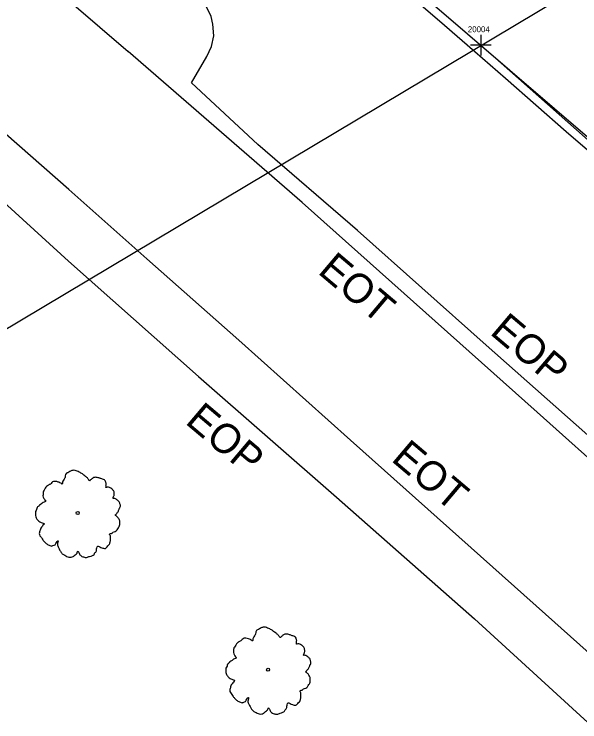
# Model space of a CAD drawing. Extents: x 2076109 to 2080761, y 592812 to 596750.
# Drawn here: x 2077285.2 to 2077381.1, y 595618.3 to 595738.3 of the extents above; entities that cross this region are included whole.
import ezdxf

# ---------------------------------------------------------------- set-up
doc = ezdxf.new("R2010")
doc.units = 0
for name, color, linetype in [('Default', 7, 'Continuous'), ('RD_EX_Misc', 7, 'Continuous'), ('RD_EX_Misc_txCode', 7, 'Continuous'), ('RD_EX_Road', 7, 'Continuous'), ('RD_EX_Road_txCode', 7, 'Continuous'), ('RD_EX_UT', 7, 'Continuous'), ('RD_EX_VEG', 7, 'Continuous'), ('RD_HC_Cl', 7, 'Continuous')]:
    doc.layers.add(name, color=color, linetype=linetype)

msp = doc.modelspace()

# ---------------------------------------------------------------- linework, layer by layer
at = {"layer": 'Default'}
for p, q in [((2077364.31, 595734.81), (2077364.31, 595731.31)), ((2077364.31, 595734.81), (2077364.31, 595731.31)), ((2077364.31, 595734.81), (2077364.31, 595731.31)), ((2077364.31, 595734.81), (2077364.31, 595731.31)), ((2077366.06, 595733.06), (2077362.56, 595733.06)), ((2077366.06, 595733.06), (2077362.56, 595733.06)), ((2077366.06, 595733.06), (2077362.56, 595733.06)), ((2077366.06, 595733.06), (2077362.56, 595733.06)), ((2077364.31, 595733.06), (2078453.96, 594769.07)), ((2077364.31, 595733.06), (2078453.96, 594769.07))]:
    msp.add_line(p, q, dxfattribs=at)
msp.add_arc((2035586.7, 547847.96), 63546.51, 48.5011873, 49.2923126, dxfattribs=at)
msp.add_arc((2035586.7, 547847.96), 63546.51, 48.5011873, 49.2923126, dxfattribs=at)
at = {"layer": 'RD_EX_Misc'}
for points in [[(2077285.72, 595748.24), (2077304.56, 595732)], [(2077285.72, 595748.24), (2077304.56, 595732)], [(2077294.47, 595708.58), (2077270.77, 595729.36), (2077263.48, 595735.7)], [(2077294.47, 595708.58), (2077270.77, 595729.36), (2077263.48, 595735.7)], [(2077850.7, 595201.63), (2077820.53, 595232.8), (2077790.22, 595263.88), (2077762.8, 595291.76), (2077736.42, 595318.96), (2077709.92, 595346.36), (2077678.72, 595378.46), (2077649.91, 595408.22), (2077612.46, 595446.3), (2077577.19, 595481.07), (2077550.3, 595507.41), (2077509.12, 595546.77), (2077481.37, 595572.73), (2077443, 595608.1), (2077400.67, 595646.86), (2077373.88, 595670.82), (2077334.03, 595706.37), (2077304.56, 595732)], [(2077850.7, 595201.63), (2077820.53, 595232.8), (2077790.22, 595263.88), (2077762.8, 595291.76), (2077736.42, 595318.96), (2077709.92, 595346.36), (2077678.72, 595378.46), (2077649.91, 595408.22), (2077612.46, 595446.3), (2077577.19, 595481.07), (2077550.3, 595507.41), (2077509.12, 595546.77), (2077481.37, 595572.73), (2077443, 595608.1), (2077400.67, 595646.86), (2077373.88, 595670.82), (2077334.03, 595706.37), (2077304.56, 595732)], [(2077812.69, 595205.74), (2077779.15, 595240.73), (2077743.86, 595277.34), (2077707.16, 595314.93), (2077677.78, 595345.17), (2077641.95, 595381.51), (2077607.57, 595416.21), (2077570.67, 595452.82), (2077540.71, 595482.36), (2077500.4, 595521.29), (2077469.88, 595550.44), (2077431.8, 595585.6), (2077401.7, 595612.91), (2077373.73, 595637.96), (2077342.22, 595666.06), (2077323.28, 595683.05), (2077307.69, 595696.83), (2077294.47, 595708.58)], [(2077812.69, 595205.74), (2077779.15, 595240.73), (2077743.86, 595277.34), (2077707.16, 595314.93), (2077677.78, 595345.17), (2077641.95, 595381.51), (2077607.57, 595416.21), (2077570.67, 595452.82), (2077540.71, 595482.36), (2077500.4, 595521.29), (2077469.88, 595550.44), (2077431.8, 595585.6), (2077401.7, 595612.91), (2077373.73, 595637.96), (2077342.22, 595666.06), (2077323.28, 595683.05), (2077307.69, 595696.83), (2077294.47, 595708.58)]]:
    msp.add_lwpolyline(points, dxfattribs=at)
at = {"layer": 'RD_EX_Road'}
for points in [[(2077528.44, 595532.32), (2077507.93, 595551.7), (2077491.72, 595567.02), (2077467.24, 595590.18), (2077449.74, 595606.14), (2077431.68, 595622.71), (2077417.63, 595635.43), (2077400.96, 595650.59), (2077383.92, 595665.65), (2077365.24, 595682.19), (2077343.44, 595701.66), (2077326.52, 595716.21), (2077315.27, 595726.7), (2077317.91, 595731.12), (2077318.69, 595732.86), (2077319.09, 595734.63), (2077318.89, 595736.63), (2077318.61, 595737.93), (2077317.61, 595740.01), (2077315.19, 595742.84)], [(2077528.44, 595532.32), (2077507.93, 595551.7), (2077491.72, 595567.02), (2077467.24, 595590.18), (2077449.74, 595606.14), (2077431.68, 595622.71), (2077417.63, 595635.43), (2077400.96, 595650.59), (2077383.92, 595665.65), (2077365.24, 595682.19), (2077343.44, 595701.66), (2077326.52, 595716.21), (2077315.27, 595726.7), (2077317.91, 595731.12), (2077318.69, 595732.86), (2077319.09, 595734.63), (2077318.89, 595736.63), (2077318.61, 595737.93), (2077317.61, 595740.01), (2077315.19, 595742.84)], [(2077277.58, 595711.76), (2077294.44, 595696.44), (2077316.48, 595676.87), (2077339.86, 595656.39), (2077363.23, 595635.78), (2077381.85, 595618.74), (2077401.46, 595601.04), (2077426.38, 595578.58), (2077449.29, 595557.26), (2077472.1, 595535.89), (2077492.72, 595516.55), (2077515.1, 595494.99), (2077537.08, 595473.82), (2077562.41, 595448.47), (2077584.67, 595425.87), (2077605.91, 595404.49), (2077629.68, 595380.24), (2077656.48, 595352.83), (2077679.73, 595328.95), (2077700.7, 595307.57), (2077723.07, 595284.36), (2077743.1, 595263.78)], [(2077277.58, 595711.76), (2077294.44, 595696.44), (2077316.48, 595676.87), (2077339.86, 595656.39), (2077363.23, 595635.78), (2077381.85, 595618.74), (2077401.46, 595601.04), (2077426.38, 595578.58), (2077449.29, 595557.26), (2077472.1, 595535.89), (2077492.72, 595516.55), (2077515.1, 595494.99), (2077537.08, 595473.82), (2077562.41, 595448.47), (2077584.67, 595425.87), (2077605.91, 595404.49), (2077629.68, 595380.24), (2077656.48, 595352.83), (2077679.73, 595328.95), (2077700.7, 595307.57), (2077723.07, 595284.36), (2077743.1, 595263.78)]]:
    msp.add_lwpolyline(points, dxfattribs=at)
at = {"layer": 'RD_EX_UT'}
msp.add_line((2077214.8, 595643.67), (2077512.89, 595821.92), dxfattribs=at)
msp.add_line((2077214.8, 595643.67), (2077512.89, 595821.92), dxfattribs=at)
at = {"layer": 'RD_EX_VEG'}
for centre, radius in [((2077295.99, 595653.73), 0.25), ((2077295.99, 595653.73), 0.25), ((2077295.97, 595653.72), 0.0001), ((2077295.97, 595653.72), 0.0001), ((2077328.27, 595627.15), 0.25), ((2077328.27, 595627.15), 0.25), ((2077328.25, 595627.14), 0.0001), ((2077328.25, 595627.14), 0.0001)]:
    msp.add_circle(centre, radius, dxfattribs=at)
for points in [[(2077300.72, 595659.12), (2077300.51, 595659.33), (2077300.2, 595659.46), (2077299.94, 595659.55), (2077299.72, 595659.64), (2077299.48, 595659.7), (2077299.14, 595659.77), (2077298.84, 595659.76), (2077298.58, 595659.65), (2077298.4, 595659.51), (2077298.19, 595659.33), (2077298.07, 595659.2), (2077297.96, 595659.26), (2077297.86, 595659.37), (2077297.72, 595659.59), (2077297.53, 595659.75), (2077297.34, 595659.92), (2077297.06, 595660.12), (2077296.79, 595660.35), (2077296.55, 595660.49), (2077296.27, 595660.66), (2077295.9, 595660.81), (2077295.55, 595660.94), (2077295.16, 595660.94), (2077294.66, 595660.74), (2077294.34, 595660.55), (2077294.07, 595660.46), (2077293.89, 595660.02), (2077293.8, 595659.64), (2077293.69, 595659.47), (2077293.47, 595659.1), (2077293.4, 595658.86), (2077293.37, 595658.63), (2077293.29, 595658.66), (2077292.98, 595658.86), (2077292.68, 595658.98), (2077292.21, 595659.08), (2077291.9, 595659.06), (2077291.61, 595658.87), (2077291.36, 595658.62), (2077291.16, 595658.53), (2077290.92, 595658.37), (2077290.86, 595658.33), (2077290.61, 595658.11), (2077290.39, 595657.71), (2077290.19, 595657.42), (2077290.14, 595657.17), (2077290.14, 595656.94), (2077290.11, 595656.64), (2077290.27, 595656.21), (2077290.45, 595655.92), (2077290.59, 595655.77), (2077290.13, 595655.5), (2077289.87, 595655.27), (2077289.52, 595655.05), (2077289.47, 595654.99), (2077289.12, 595654.66), (2077289.03, 595654.31), (2077288.84, 595653.98), (2077288.83, 595653.69), (2077288.85, 595653.29), (2077288.95, 595652.91), (2077289.25, 595652.49), (2077289.57, 595652.25), (2077290.12, 595652.01), (2077290.36, 595651.91), (2077290.23, 595651.79), (2077290.01, 595651.49), (2077289.73, 595651.16), (2077289.64, 595650.82), (2077289.54, 595650.54), (2077289.49, 595650.26), (2077289.59, 595649.87), (2077289.85, 595649.56), (2077290.08, 595649.17), (2077290.37, 595648.82), (2077290.74, 595648.48), (2077291.29, 595648.21), (2077291.58, 595648.12), (2077291.77, 595648.19), (2077292.17, 595648.35), (2077292.27, 595648.55), (2077292.68, 595649), (2077292.64, 595648.8), (2077292.55, 595648.42), (2077292.74, 595647.87), (2077292.93, 595647.47), (2077293.2, 595647.05), (2077293.38, 595646.8), (2077293.79, 595646.55), (2077294.12, 595646.37), (2077294.49, 595646.22), (2077294.9, 595646.24), (2077295.21, 595646.33), (2077295.42, 595646.51), (2077295.72, 595646.75), (2077295.87, 595646.85)], [(2077300.72, 595659.12), (2077300.51, 595659.33), (2077300.2, 595659.46), (2077299.94, 595659.55), (2077299.72, 595659.64), (2077299.48, 595659.7), (2077299.14, 595659.77), (2077298.84, 595659.76), (2077298.58, 595659.65), (2077298.4, 595659.51), (2077298.19, 595659.33), (2077298.07, 595659.2), (2077297.96, 595659.26), (2077297.86, 595659.37), (2077297.72, 595659.59), (2077297.53, 595659.75), (2077297.34, 595659.92), (2077297.06, 595660.12), (2077296.79, 595660.35), (2077296.55, 595660.49), (2077296.27, 595660.66), (2077295.9, 595660.81), (2077295.55, 595660.94), (2077295.16, 595660.94), (2077294.66, 595660.74), (2077294.34, 595660.55), (2077294.07, 595660.46), (2077293.89, 595660.02), (2077293.8, 595659.64), (2077293.69, 595659.47), (2077293.47, 595659.1), (2077293.4, 595658.86), (2077293.37, 595658.63), (2077293.29, 595658.66), (2077292.98, 595658.86), (2077292.68, 595658.98), (2077292.21, 595659.08), (2077291.9, 595659.06), (2077291.61, 595658.87), (2077291.36, 595658.62), (2077291.16, 595658.53), (2077290.92, 595658.37), (2077290.86, 595658.33), (2077290.61, 595658.11), (2077290.39, 595657.71), (2077290.19, 595657.42), (2077290.14, 595657.17), (2077290.14, 595656.94), (2077290.11, 595656.64), (2077290.27, 595656.21), (2077290.45, 595655.92), (2077290.59, 595655.77), (2077290.13, 595655.5), (2077289.87, 595655.27), (2077289.52, 595655.05), (2077289.47, 595654.99), (2077289.12, 595654.66), (2077289.03, 595654.31), (2077288.84, 595653.98), (2077288.83, 595653.69), (2077288.85, 595653.29), (2077288.95, 595652.91), (2077289.25, 595652.49), (2077289.57, 595652.25), (2077290.12, 595652.01), (2077290.36, 595651.91), (2077290.23, 595651.79), (2077290.01, 595651.49), (2077289.73, 595651.16), (2077289.64, 595650.82), (2077289.54, 595650.54), (2077289.49, 595650.26), (2077289.59, 595649.87), (2077289.85, 595649.56), (2077290.08, 595649.17), (2077290.37, 595648.82), (2077290.74, 595648.48), (2077291.29, 595648.21), (2077291.58, 595648.12), (2077291.77, 595648.19), (2077292.17, 595648.35), (2077292.27, 595648.55), (2077292.68, 595649), (2077292.64, 595648.8), (2077292.55, 595648.42), (2077292.74, 595647.87), (2077292.93, 595647.47), (2077293.2, 595647.05), (2077293.38, 595646.8), (2077293.79, 595646.55), (2077294.12, 595646.37), (2077294.49, 595646.22), (2077294.9, 595646.24), (2077295.21, 595646.33), (2077295.42, 595646.51), (2077295.72, 595646.75), (2077295.87, 595646.85)], [(2077295.87, 595646.85), (2077295.93, 595647.03), (2077296.05, 595647.26), (2077296.09, 595647.19), (2077296.19, 595647.04), (2077296.32, 595646.76), (2077296.45, 595646.56), (2077296.71, 595646.37), (2077296.99, 595646.27), (2077297.51, 595646.19), (2077298.02, 595646.37), (2077298.49, 595646.5), (2077298.76, 595646.7), (2077298.87, 595646.9), (2077299.17, 595647.3), (2077299.18, 595647.62), (2077299.22, 595647.75), (2077299.4, 595648.12), (2077299.49, 595648.11), (2077299.73, 595647.97), (2077300.1, 595647.82), (2077300.39, 595647.74), (2077300.68, 595647.73), (2077300.88, 595647.85), (2077301.12, 595648.17), (2077301.41, 595648.45), (2077301.45, 595648.61), (2077301.47, 595648.79), (2077301.55, 595648.99), (2077301.53, 595649.2), (2077301.55, 595649.38), (2077301.54, 595649.52), (2077301.54, 595649.72), (2077301.49, 595649.92), (2077301.4, 595650.06), (2077301.46, 595650.21), (2077301.71, 595650.26), (2077301.81, 595650.31), (2077301.97, 595650.46), (2077302.37, 595650.58), (2077302.67, 595650.86), (2077302.9, 595651.21), (2077303.04, 595651.45), (2077303.11, 595651.76), (2077303.12, 595652.08), (2077303.13, 595652.3), (2077303.08, 595652.5), (2077302.91, 595652.81), (2077302.75, 595653.01), (2077302.49, 595653.23), (2077302.37, 595653.4), (2077302.42, 595653.42), (2077302.52, 595653.54), (2077302.69, 595653.75), (2077302.93, 595654.14), (2077303.13, 595654.62), (2077303.15, 595654.64), (2077303.24, 595654.89), (2077303.19, 595655.19), (2077303.12, 595655.38), (2077303.05, 595655.6), (2077302.88, 595655.79), (2077302.65, 595655.98), (2077302.41, 595656.12), (2077302.19, 595656.17), (2077301.98, 595656.19), (2077302.02, 595656.35), (2077302.13, 595656.65), (2077302.19, 595656.79), (2077302.19, 595657.02), (2077302.15, 595657.32), (2077301.88, 595657.71), (2077301.36, 595658.05), (2077301, 595658.09), (2077300.77, 595658.06), (2077300.82, 595658.18), (2077300.79, 595658.47), (2077300.83, 595658.66), (2077300.78, 595658.87), (2077300.73, 595659.05), (2077300.68, 595659.15)], [(2077295.87, 595646.85), (2077295.93, 595647.03), (2077296.05, 595647.26), (2077296.09, 595647.19), (2077296.19, 595647.04), (2077296.32, 595646.76), (2077296.45, 595646.56), (2077296.71, 595646.37), (2077296.99, 595646.27), (2077297.51, 595646.19), (2077298.02, 595646.37), (2077298.49, 595646.5), (2077298.76, 595646.7), (2077298.87, 595646.9), (2077299.17, 595647.3), (2077299.18, 595647.62), (2077299.22, 595647.75), (2077299.4, 595648.12), (2077299.49, 595648.11), (2077299.73, 595647.97), (2077300.1, 595647.82), (2077300.39, 595647.74), (2077300.68, 595647.73), (2077300.88, 595647.85), (2077301.12, 595648.17), (2077301.41, 595648.45), (2077301.45, 595648.61), (2077301.47, 595648.79), (2077301.55, 595648.99), (2077301.53, 595649.2), (2077301.55, 595649.38), (2077301.54, 595649.52), (2077301.54, 595649.72), (2077301.49, 595649.92), (2077301.4, 595650.06), (2077301.46, 595650.21), (2077301.71, 595650.26), (2077301.81, 595650.31), (2077301.97, 595650.46), (2077302.37, 595650.58), (2077302.67, 595650.86), (2077302.9, 595651.21), (2077303.04, 595651.45), (2077303.11, 595651.76), (2077303.12, 595652.08), (2077303.13, 595652.3), (2077303.08, 595652.5), (2077302.91, 595652.81), (2077302.75, 595653.01), (2077302.49, 595653.23), (2077302.37, 595653.4), (2077302.42, 595653.42), (2077302.52, 595653.54), (2077302.69, 595653.75), (2077302.93, 595654.14), (2077303.13, 595654.62), (2077303.15, 595654.64), (2077303.24, 595654.89), (2077303.19, 595655.19), (2077303.12, 595655.38), (2077303.05, 595655.6), (2077302.88, 595655.79), (2077302.65, 595655.98), (2077302.41, 595656.12), (2077302.19, 595656.17), (2077301.98, 595656.19), (2077302.02, 595656.35), (2077302.13, 595656.65), (2077302.19, 595656.79), (2077302.19, 595657.02), (2077302.15, 595657.32), (2077301.88, 595657.71), (2077301.36, 595658.05), (2077301, 595658.09), (2077300.77, 595658.06), (2077300.82, 595658.18), (2077300.79, 595658.47), (2077300.83, 595658.66), (2077300.78, 595658.87), (2077300.73, 595659.05), (2077300.68, 595659.15)], [(2077333, 595632.53), (2077332.79, 595632.74), (2077332.48, 595632.88), (2077332.22, 595632.96), (2077332, 595633.05), (2077331.77, 595633.12), (2077331.42, 595633.18), (2077331.12, 595633.17), (2077330.87, 595633.06), (2077330.68, 595632.92), (2077330.47, 595632.75), (2077330.35, 595632.61), (2077330.24, 595632.67), (2077330.14, 595632.79), (2077330, 595633.01), (2077329.81, 595633.17), (2077329.62, 595633.33), (2077329.34, 595633.54), (2077329.07, 595633.76), (2077328.83, 595633.9), (2077328.55, 595634.08), (2077328.18, 595634.22), (2077327.83, 595634.35), (2077327.44, 595634.36), (2077326.95, 595634.16), (2077326.62, 595633.97), (2077326.35, 595633.88), (2077326.17, 595633.43), (2077326.08, 595633.05), (2077325.97, 595632.89), (2077325.75, 595632.51), (2077325.68, 595632.28), (2077325.65, 595632.04), (2077325.58, 595632.07), (2077325.26, 595632.28), (2077324.96, 595632.39), (2077324.5, 595632.5), (2077324.18, 595632.47), (2077323.89, 595632.29), (2077323.65, 595632.04), (2077323.44, 595631.95), (2077323.21, 595631.79), (2077323.14, 595631.75), (2077322.89, 595631.53), (2077322.68, 595631.12), (2077322.47, 595630.84), (2077322.42, 595630.59), (2077322.42, 595630.36), (2077322.39, 595630.05), (2077322.55, 595629.62), (2077322.74, 595629.34), (2077322.87, 595629.19), (2077322.42, 595628.92), (2077322.15, 595628.69), (2077321.8, 595628.46), (2077321.75, 595628.4), (2077321.41, 595628.07), (2077321.31, 595627.73), (2077321.13, 595627.39), (2077321.11, 595627.11), (2077321.13, 595626.7), (2077321.23, 595626.32), (2077321.53, 595625.9), (2077321.85, 595625.66), (2077322.41, 595625.43), (2077322.65, 595625.32), (2077322.51, 595625.2), (2077322.29, 595624.9), (2077322.02, 595624.58), (2077321.92, 595624.23), (2077321.82, 595623.96), (2077321.77, 595623.67), (2077321.88, 595623.29), (2077322.13, 595622.97), (2077322.36, 595622.59), (2077322.65, 595622.24), (2077323.02, 595621.9), (2077323.57, 595621.62), (2077323.86, 595621.54), (2077324.05, 595621.61), (2077324.45, 595621.77), (2077324.56, 595621.97), (2077324.96, 595622.41), (2077324.93, 595622.21), (2077324.83, 595621.83), (2077325.02, 595621.28), (2077325.21, 595620.89), (2077325.48, 595620.47), (2077325.66, 595620.22), (2077326.07, 595619.97), (2077326.4, 595619.78), (2077326.77, 595619.64), (2077327.18, 595619.65), (2077327.49, 595619.75), (2077327.7, 595619.93), (2077328, 595620.16), (2077328.16, 595620.27)], [(2077333, 595632.53), (2077332.79, 595632.74), (2077332.48, 595632.88), (2077332.22, 595632.96), (2077332, 595633.05), (2077331.77, 595633.12), (2077331.42, 595633.18), (2077331.12, 595633.17), (2077330.87, 595633.06), (2077330.68, 595632.92), (2077330.47, 595632.75), (2077330.35, 595632.61), (2077330.24, 595632.67), (2077330.14, 595632.79), (2077330, 595633.01), (2077329.81, 595633.17), (2077329.62, 595633.33), (2077329.34, 595633.54), (2077329.07, 595633.76), (2077328.83, 595633.9), (2077328.55, 595634.08), (2077328.18, 595634.22), (2077327.83, 595634.35), (2077327.44, 595634.36), (2077326.95, 595634.16), (2077326.62, 595633.97), (2077326.35, 595633.88), (2077326.17, 595633.43), (2077326.08, 595633.05), (2077325.97, 595632.89), (2077325.75, 595632.51), (2077325.68, 595632.28), (2077325.65, 595632.04), (2077325.58, 595632.07), (2077325.26, 595632.28), (2077324.96, 595632.39), (2077324.5, 595632.5), (2077324.18, 595632.47), (2077323.89, 595632.29), (2077323.65, 595632.04), (2077323.44, 595631.95), (2077323.21, 595631.79), (2077323.14, 595631.75), (2077322.89, 595631.53), (2077322.68, 595631.12), (2077322.47, 595630.84), (2077322.42, 595630.59), (2077322.42, 595630.36), (2077322.39, 595630.05), (2077322.55, 595629.62), (2077322.74, 595629.34), (2077322.87, 595629.19), (2077322.42, 595628.92), (2077322.15, 595628.69), (2077321.8, 595628.46), (2077321.75, 595628.4), (2077321.41, 595628.07), (2077321.31, 595627.73), (2077321.13, 595627.39), (2077321.11, 595627.11), (2077321.13, 595626.7), (2077321.23, 595626.32), (2077321.53, 595625.9), (2077321.85, 595625.66), (2077322.41, 595625.43), (2077322.65, 595625.32), (2077322.51, 595625.2), (2077322.29, 595624.9), (2077322.02, 595624.58), (2077321.92, 595624.23), (2077321.82, 595623.96), (2077321.77, 595623.67), (2077321.88, 595623.29), (2077322.13, 595622.97), (2077322.36, 595622.59), (2077322.65, 595622.24), (2077323.02, 595621.9), (2077323.57, 595621.62), (2077323.86, 595621.54), (2077324.05, 595621.61), (2077324.45, 595621.77), (2077324.56, 595621.97), (2077324.96, 595622.41), (2077324.93, 595622.21), (2077324.83, 595621.83), (2077325.02, 595621.28), (2077325.21, 595620.89), (2077325.48, 595620.47), (2077325.66, 595620.22), (2077326.07, 595619.97), (2077326.4, 595619.78), (2077326.77, 595619.64), (2077327.18, 595619.65), (2077327.49, 595619.75), (2077327.7, 595619.93), (2077328, 595620.16), (2077328.16, 595620.27)], [(2077328.16, 595620.27), (2077328.21, 595620.45), (2077328.33, 595620.67), (2077328.38, 595620.6), (2077328.48, 595620.45), (2077328.61, 595620.18), (2077328.73, 595619.98), (2077328.99, 595619.79), (2077329.27, 595619.69), (2077329.79, 595619.6), (2077330.31, 595619.79), (2077330.77, 595619.92), (2077331.04, 595620.12), (2077331.15, 595620.32), (2077331.45, 595620.72), (2077331.46, 595621.04), (2077331.5, 595621.17), (2077331.68, 595621.54), (2077331.77, 595621.52), (2077332.02, 595621.39), (2077332.38, 595621.24), (2077332.67, 595621.16), (2077332.96, 595621.14), (2077333.16, 595621.27), (2077333.4, 595621.59), (2077333.7, 595621.86), (2077333.74, 595622.03), (2077333.76, 595622.2), (2077333.83, 595622.41), (2077333.81, 595622.62), (2077333.83, 595622.8), (2077333.82, 595622.94), (2077333.82, 595623.13), (2077333.77, 595623.34), (2077333.69, 595623.48), (2077333.74, 595623.62), (2077333.99, 595623.68), (2077334.09, 595623.72), (2077334.26, 595623.88), (2077334.65, 595624), (2077334.95, 595624.27), (2077335.19, 595624.63), (2077335.33, 595624.87), (2077335.39, 595625.18), (2077335.4, 595625.5), (2077335.41, 595625.71), (2077335.36, 595625.92), (2077335.19, 595626.22), (2077335.04, 595626.42), (2077334.77, 595626.65), (2077334.65, 595626.82), (2077334.7, 595626.84), (2077334.8, 595626.95), (2077334.97, 595627.16), (2077335.21, 595627.56), (2077335.42, 595628.03), (2077335.43, 595628.05), (2077335.52, 595628.31), (2077335.48, 595628.61), (2077335.41, 595628.8), (2077335.33, 595629.02), (2077335.16, 595629.2), (2077334.93, 595629.39), (2077334.69, 595629.53), (2077334.47, 595629.59), (2077334.26, 595629.6), (2077334.3, 595629.77), (2077334.41, 595630.06), (2077334.47, 595630.21), (2077334.47, 595630.44), (2077334.43, 595630.74), (2077334.17, 595631.12), (2077333.64, 595631.47), (2077333.28, 595631.51), (2077333.06, 595631.47), (2077333.1, 595631.6), (2077333.07, 595631.88), (2077333.11, 595632.08), (2077333.06, 595632.29), (2077333.01, 595632.46), (2077332.96, 595632.56)], [(2077328.16, 595620.27), (2077328.21, 595620.45), (2077328.33, 595620.67), (2077328.38, 595620.6), (2077328.48, 595620.45), (2077328.61, 595620.18), (2077328.73, 595619.98), (2077328.99, 595619.79), (2077329.27, 595619.69), (2077329.79, 595619.6), (2077330.31, 595619.79), (2077330.77, 595619.92), (2077331.04, 595620.12), (2077331.15, 595620.32), (2077331.45, 595620.72), (2077331.46, 595621.04), (2077331.5, 595621.17), (2077331.68, 595621.54), (2077331.77, 595621.52), (2077332.02, 595621.39), (2077332.38, 595621.24), (2077332.67, 595621.16), (2077332.96, 595621.14), (2077333.16, 595621.27), (2077333.4, 595621.59), (2077333.7, 595621.86), (2077333.74, 595622.03), (2077333.76, 595622.2), (2077333.83, 595622.41), (2077333.81, 595622.62), (2077333.83, 595622.8), (2077333.82, 595622.94), (2077333.82, 595623.13), (2077333.77, 595623.34), (2077333.69, 595623.48), (2077333.74, 595623.62), (2077333.99, 595623.68), (2077334.09, 595623.72), (2077334.26, 595623.88), (2077334.65, 595624), (2077334.95, 595624.27), (2077335.19, 595624.63), (2077335.33, 595624.87), (2077335.39, 595625.18), (2077335.4, 595625.5), (2077335.41, 595625.71), (2077335.36, 595625.92), (2077335.19, 595626.22), (2077335.04, 595626.42), (2077334.77, 595626.65), (2077334.65, 595626.82), (2077334.7, 595626.84), (2077334.8, 595626.95), (2077334.97, 595627.16), (2077335.21, 595627.56), (2077335.42, 595628.03), (2077335.43, 595628.05), (2077335.52, 595628.31), (2077335.48, 595628.61), (2077335.41, 595628.8), (2077335.33, 595629.02), (2077335.16, 595629.2), (2077334.93, 595629.39), (2077334.69, 595629.53), (2077334.47, 595629.59), (2077334.26, 595629.6), (2077334.3, 595629.77), (2077334.41, 595630.06), (2077334.47, 595630.21), (2077334.47, 595630.44), (2077334.43, 595630.74), (2077334.17, 595631.12), (2077333.64, 595631.47), (2077333.28, 595631.51), (2077333.06, 595631.47), (2077333.1, 595631.6), (2077333.07, 595631.88), (2077333.11, 595632.08), (2077333.06, 595632.29), (2077333.01, 595632.46), (2077332.96, 595632.56)]]:
    msp.add_spline(points, degree=3, dxfattribs=at)
at = {"layer": 'RD_HC_Cl'}
msp.add_line((2076186.59, 596746.26), (2077404.89, 595698.18), dxfattribs=at)

# ---------------------------------------------------------------- texts
at = {"layer": 'Default'}
msp.add_text('20004', height=1, dxfattribs=at).set_placement((2077362.12, 595735.26))
msp.add_text('20004', height=1, dxfattribs=at).set_placement((2077362.12, 595735.26))
at = {"layer": 'RD_EX_Misc_txCode'}
for p in [(2077336.52, 595694.48), (2077336.52, 595694.48), (2077348.96, 595662.67), (2077348.96, 595662.67)]:
    msp.add_text('EOT', height=5, rotation=319.7592, dxfattribs=at).set_placement(p)
at = {"layer": 'RD_EX_Road_txCode'}
for p in [(2077365.69, 595684.18), (2077365.69, 595684.18), (2077314.05, 595669.01), (2077314.05, 595669.01)]:
    msp.add_text('EOP', height=5, rotation=319.7592, dxfattribs=at).set_placement(p)

doc.saveas('drawing.dxf')
